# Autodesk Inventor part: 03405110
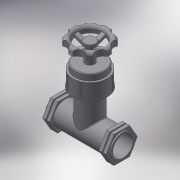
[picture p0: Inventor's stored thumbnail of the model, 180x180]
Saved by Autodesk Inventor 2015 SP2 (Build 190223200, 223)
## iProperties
Created: 2017-05
Part Number: 03405110
Material: Generic
Description: PLASSON THREADED STOPTAP 1"
Document SubType Name: Modeling
Designer: KIM
Mass: 78.2644 g
Surface Area: 269.076 cm^2
Volume: 78.2644 cm^3
Density: 1 g/cm^3
Appearance: Default
Author: KIM
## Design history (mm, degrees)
derived "03405.ipt"
feature "Solid1::03405.ipt"
tag "TaggingFeature1"
body "Solid1"
other parameters: "d13" = 13.5, "d17" = 35.88, "d19" = 59.8, "d22" = 27.6, "d23" = 18.4, "d24" = 41.4, "d25" = 11.04, "d26" = 90 deg, "d27" = 32.2, "d28" = 70 deg, "d29" = 13.8, "d30" = 11.04, "d31" = 13.8, "d32" = 46, "d33" = 32.2, "d36" = 92, "d41" = 1, "d43" = 2.76, "d44" = 2.76, "d46" = 0, "d48" = 360 deg, "d50" = 0.46, "d51" = 0.46, "d53" = 360 deg, "d69" = 39.1, "d70" = 2.76, "d71" = 2.76, "d72" = 5.52, "d74" = 0, "d75" = 0.46, "d77" = 360 deg, "d80" = 40.158, "d81" = 13.8, "d82" = 6.9, "d83" = 16.56, "d84" = 0, "d86" = 360 deg, "d88" = 0.92, "d89" = 7.36, "d90" = 30.291, "d91" = 82, "d94" = 36.3492, "d95" = 4, "d96" = 1.6, "d97" = 27.2619, "d100" = 0, "d104" = 0, "d106" = 0, "d107" = 0.92, "d108" = 0.644, "d111" = 92, "H_" = 82, "R_" = 30.291, "A_" = 92, "d67" = 46, "d68" = 32.2, "d79" = 41.4
